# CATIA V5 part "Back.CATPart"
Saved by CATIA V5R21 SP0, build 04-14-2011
Part number: Back
Material "Gold Metal": density 7860 kg/m3, Young's modulus 2e+11 Pa, Poisson ratio 0.266
Bounding box of the stored display mesh (mm): x 0 to 5, y -50 to 50, z 0 to 57.339
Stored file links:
  G:\CATIA\Class\Project_2\Back.CATPart
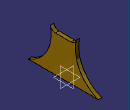
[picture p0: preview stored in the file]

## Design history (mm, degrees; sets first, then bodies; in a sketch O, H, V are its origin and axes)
Body1 (main body), material "Gold Metal"
  Sketch1 on yz-plane, origin (0, 0, 0), H (0, 1, 0), V (0, 0, 1)
    line L1 (0, 0) -> (50, 0)
    point P1 (50, 0)
    point P2 (-50, 0)
    point P3 (0, 0)
    line L2 (0, 0) -> (-50, 0)
    construction line L3 (11, 58.9) -> (-11, 58.9)
    point P4 (11, 58.9)
    point P5 (-11, 58.9)
    line L4 (11, 51.4) -> (-11, 51.4)
    arc A1 centre (-11, 58.9) radius 7.5 from (-11, 51.4) to (-18.3358, 57.3391) cw
    arc A2 centre (11, 58.9) radius 7.5 from (18.3358, 57.3391) to (11, 51.4) cw
    construction line L5 (11, 58.9) -> (-11, 58.9)
    arc A3 centre (-67.241, 46.9334) radius 50 from (-50, 0) to (-18.3358, 57.3391) ccw
    point P9 (50, 0)
    arc A4 centre (67.241, 46.9334) radius 50 from (50, 0) to (18.3358, 57.3391) cw
    length L1 = 50
    distance L3 L4 = 7.5
    distance P4 V = 11
    distance P5 V = 11
    distance L5 L1 = 58.9
    radius A3 = 50
    horizontal: L1 H, L3 H, L5 H
    symmetry: P1 P2 V, O P3 V, L1 L2 V, P2 P9 V, A3 A4 V
    tangency: A1 L4, A2 L4, A3 A1
    coincidence: O P3, P1 P9
  Pad1: profile Sketch1, direction (1, 0, 0), length 5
